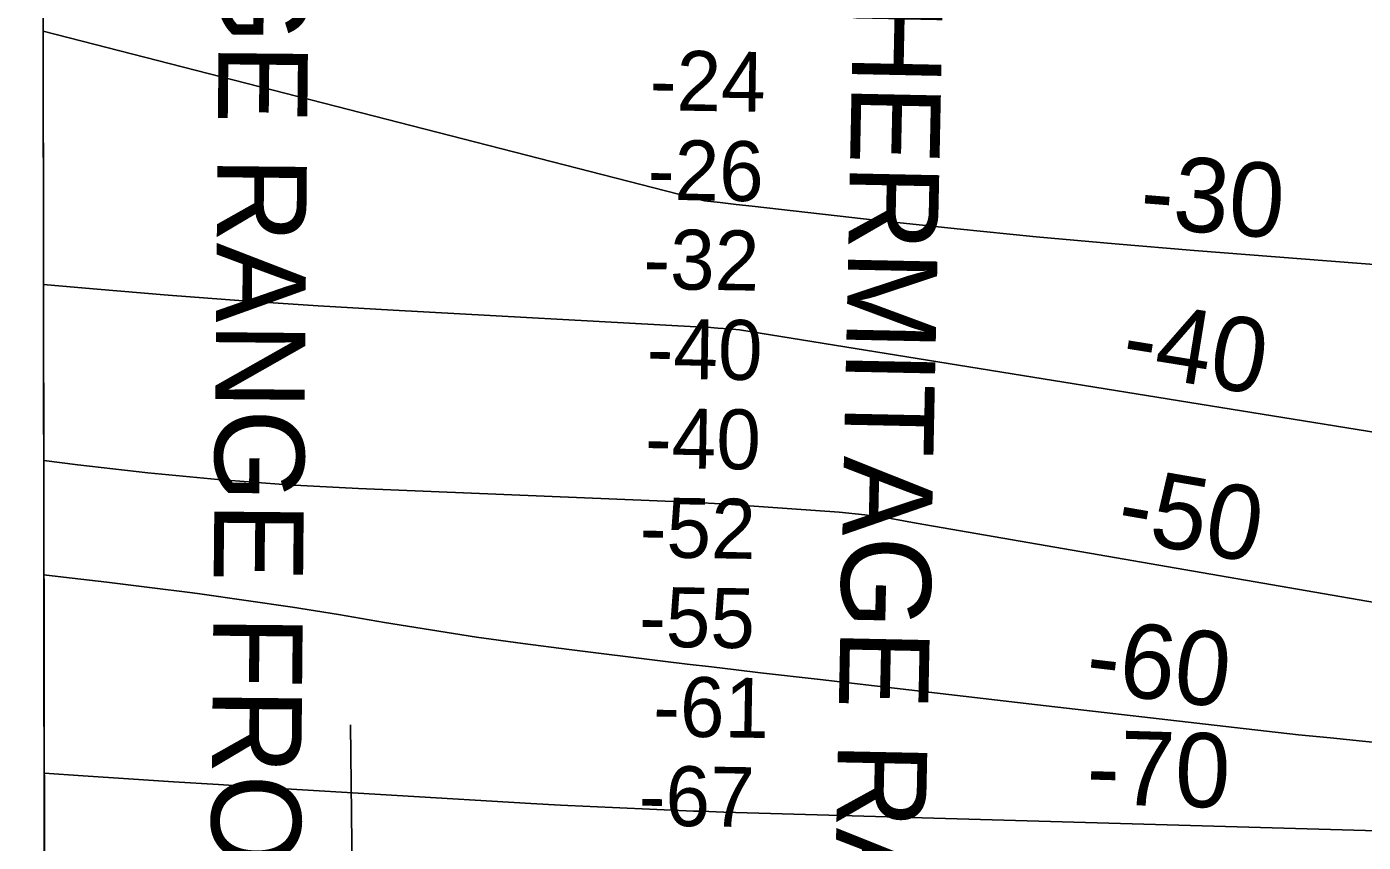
# Model space of a CAD drawing. Extents: x 3329297 to 3367176, y 649250 to 674653.
# Drawn here: x 3333403 to 3334898, y 659315 to 660227 of the extents above; entities that cross this region are included whole.
import ezdxf

# ---------------------------------------------------------------- set-up
doc = ezdxf.new("R2010")
doc.units = 0
for name, color, linetype in [('V-CHAN-NAID', 7, 'Continuous'), ('V-GRID-FRAM', 7, 'Continuous'), ('V-RIVR-RANG', 7, 'Continuous'), ('V-TOPO-DPTH', 7, 'Continuous'), ('V-TOPO-MAJR', 7, 'Continuous'), ('V-TOPO-MAJR-IDEN', 7, 'Continuous'), ('V-TOPO-MINR', 7, 'Continuous'), ('V-TOPO-MINR-IDEN', 7, 'Continuous')]:
    doc.layers.add(name, color=color, linetype=linetype)

msp = doc.modelspace()

# ---------------------------------------------------------------- linework, layer by layer
at = {"layer": 'V-GRID-FRAM'}
msp.add_lwpolyline([(3333403.5, 672816.3), (3364945.5, 672875.9), (3364987.9, 654691.7), (3333429.9, 654632), (3333403.5, 672816.3)], dxfattribs=at)
at = {"layer": 'V-RIVR-RANG'}
msp.add_line((3333780.1, 658206), (3333765.7, 659446), dxfattribs=at)
at = {"layer": 'V-TOPO-DPTH'}
msp.add_line((3333423.6, 659024.9), (3333422.2, 659938.5), dxfattribs=at)
for points in [[(3333421.8, 660221.9), (3333421.4, 660507.3)], [(3334953.3, 659957.5), (3334709.3, 659976.6), (3334620.8, 659984), (3334532.4, 659991.9), (3334444, 660000.7), (3334355.7, 660010.2), (3334214.8, 660025.9), (3334197, 660027.9), (3334179.2, 660030), (3334161.4, 660032.1), (3333421.8, 660221.9)], [(3333422.2, 659938.5), (3333421.8, 660221.9), (3334161.4, 660032.1), (3334179.2, 660030), (3334197, 660027.9), (3334214.8, 660025.9), (3334355.7, 660010.2), (3334444, 660000.7), (3334532.4, 659991.9), (3334620.8, 659984), (3334709.3, 659976.6), (3334953.3, 659957.5)], [(3334960.7, 659765.2), (3334200.8, 659887.9), (3334188.7, 659888.9), (3334176.6, 659889.8), (3334164.4, 659890.6), (3334152.3, 659891.3), (3333813.3, 659909.8), (3333729.3, 659914.7), (3333645.4, 659920.3), (3333561.5, 659926.7), (3333477.7, 659933.6), (3333422.2, 659938.5)], [(3333422.2, 659938.5), (3333477.7, 659933.6), (3333561.5, 659926.7), (3333645.4, 659920.3), (3333729.3, 659914.7), (3333813.3, 659909.8), (3334152.3, 659891.3), (3334164.4, 659890.6), (3334176.6, 659889.8), (3334188.7, 659888.9), (3334200.8, 659887.9), (3334960.7, 659765.2)]]:
    msp.add_lwpolyline(points, dxfattribs=at)
at = {"layer": 'V-TOPO-MAJR'}
msp.add_lwpolyline([(3334999.3, 659567.7), (3334398.3, 659671.6), (3334369.8, 659676.9), (3334341, 659680.8), (3334312, 659683.7), (3334200.9, 659691.8), (3334186.9, 659692.7), (3334172.9, 659693.6), (3334158.9, 659694.3), (3334144.9, 659695), (3333774.4, 659710.4), (3333695.7, 659714.6), (3333617.2, 659720.2), (3333538.8, 659727.8), (3333460.6, 659736.7), (3333422.5, 659741.5)], dxfattribs=at)
at = {"layer": 'V-TOPO-MINR'}
for points in [[(3334953.3, 659957.5), (3334709.3, 659976.6), (3334620.8, 659984), (3334532.4, 659991.9), (3334444, 660000.7), (3334355.7, 660010.2), (3334214.8, 660025.9), (3334197, 660027.9), (3334179.2, 660030), (3334161.4, 660032.1), (3333421.8, 660221.9)], [(3334960.7, 659765.2), (3334200.8, 659887.9), (3334188.7, 659888.9), (3334176.6, 659889.8), (3334164.4, 659890.6), (3334152.3, 659891.3), (3333813.3, 659909.8), (3333729.3, 659914.7), (3333645.4, 659920.3), (3333561.5, 659926.7), (3333477.7, 659933.6), (3333422.2, 659938.5)], [(3334938.7, 659423.7), (3334897.5, 659427.7), (3334861.7, 659431.3), (3334825.9, 659435), (3334790.1, 659438.9), (3334754.4, 659442.9), (3334533.9, 659468.5), (3334473.1, 659475.5), (3334412.4, 659482.5), (3334351.7, 659489.5), (3334291, 659496.6), (3334224.3, 659504.3), (3334196.9, 659507.5), (3334169.5, 659510.7), (3334142.1, 659514), (3334114.8, 659517.3), (3334010.2, 659530.1), (3333958.4, 659536.8), (3333906.7, 659544), (3333855.2, 659552.1), (3333803.6, 659560.6), (3333752.1, 659569.3), (3333700.6, 659577.5), (3333648.9, 659585.1), (3333597.2, 659592.4), (3333588.9, 659593.5), (3333540.9, 659599.7), (3333492.9, 659605.7), (3333444.8, 659611.3), (3333422.7, 659613.8)], [(3333423, 659391.9), (3333466.8, 659388.9), (3333517.2, 659385.6), (3333567.6, 659382.3), (3333618, 659379.1), (3333668.4, 659376), (3333967.3, 659358.2), (3334000.4, 659356.3), (3334033.6, 659354.6), (3334066.8, 659353), (3334099.9, 659351.6), (3334149.4, 659349.6), (3334157.8, 659349.3), (3334166.3, 659349), (3334174.7, 659348.7), (3334183.1, 659348.4), (3335018.4, 659324.5)]]:
    msp.add_lwpolyline(points, dxfattribs=at)

# ---------------------------------------------------------------- texts
at = {"layer": 'V-CHAN-NAID'}
for s, rotation, p in [('OLD HERMITAGE RANGE FRONT (213.4)', 269.4744, (3333627.4, 661226)), ('OLD HERMITAGE RANGE REAR', 268.8144, (3334334.6, 660571.5))]:
    msp.add_text(s, height=100, rotation=rotation, dxfattribs=at).set_placement(p)
at = {"layer": 'V-RIVR-RANG'}
for s, p in [('-24', (3334100, 660133.5)), ('-26', (3334097.8, 660033.5)), ('-32', (3334092.8, 659933.6)), ('-40', (3334096.5, 659833.5)), ('-40', (3334094.6, 659733.5)), ('-52', (3334088.8, 659633.6)), ('-55', (3334088, 659533.6)), ('-61', (3334103.8, 659433.3)), ('-67', (3334087.6, 659333.6))]:
    msp.add_text(s, height=67, rotation=359.0721, dxfattribs=at).set_placement(p)
at = {"layer": 'V-TOPO-MAJR-IDEN'}
msp.add_text('-50', height=83, rotation=350.1964, dxfattribs=at).set_placement((3334619.9, 659654.3))
at = {"layer": 'V-TOPO-MINR-IDEN'}
for s, rotation, p in [('-30', 355.5308, (3334646.9, 660002.3)), ('-40', 350.8262, (3334625.4, 659840.4)), ('-60', 353.394, (3334585.6, 659483.4)), ('-70', 358.3587, (3334588.1, 659357.6))]:
    msp.add_text(s, height=83, rotation=rotation, dxfattribs=at).set_placement(p)

doc.saveas('drawing.dxf')
